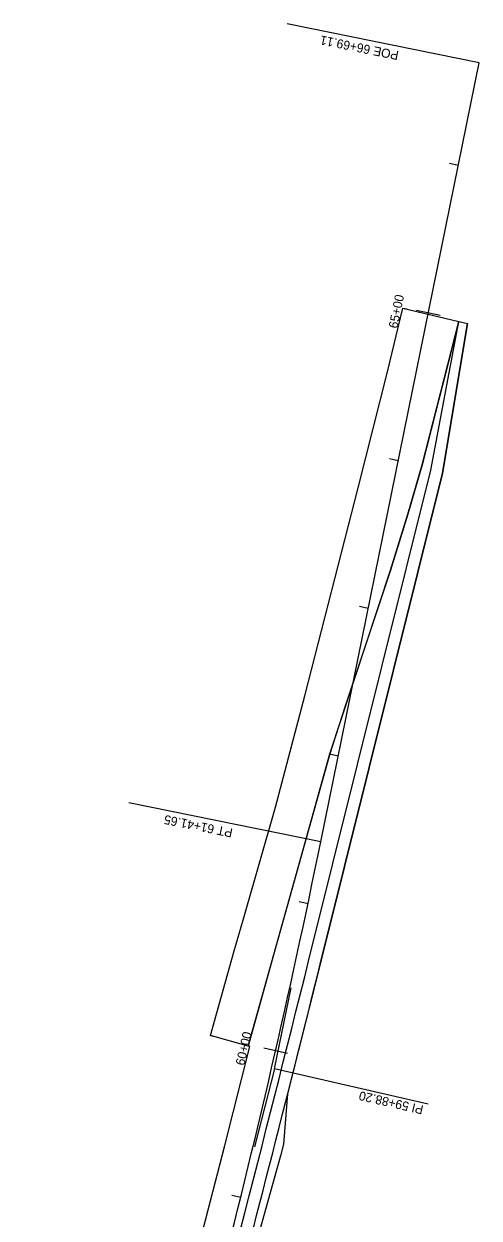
# Model space of a CAD drawing. Extents: x 1445613 to 1446340, y 2042797 to 2056486.
# Drawn here: x 1446038 to 1446340, y 2055693 to 2056486 of the extents above; entities that cross this region are included whole.
import ezdxf

# ---------------------------------------------------------------- set-up
doc = ezdxf.new("R2010")
doc.units = 0
for name, color, linetype in [('20', 7, 'Continuous'), ('Default', 7, 'Continuous'), ('R_Horz Alg', 7, 'Continuous'), ('R_Horz Alg Annot', 7, 'Continuous'), ('R_Horz Alg Annot_Detour', 7, 'Continuous'), ('R_Horz Alg Stationing_Detour', 7, 'Continuous'), ('R_Proposed Road', 7, 'Continuous')]:
    doc.layers.add(name, color=color, linetype=linetype)

msp = doc.modelspace()

# ---------------------------------------------------------------- linework, layer by layer
at = {"layer": '20'}
msp.add_lwpolyline([(1446186.83, 2055807.56), (1446161.85, 2055814.6), (1446177.63, 2055870.73), (1446183.69, 2055891.92), (1446205.01, 2055966.11), (1446224.41, 2056039.93), (1446259.82, 2056178.04), (1446279.28, 2056254.8), (1446289.65, 2056297.22), (1446326.65, 2056288.39), (1446311.26, 2056227.87), (1446302.34, 2056193.19), (1446292.95, 2056160.46), (1446281.38, 2056123.41), (1446261.62, 2056064.35), (1446251, 2056032.33), (1446241.05, 2056001.36), (1446205.13, 2055872.64)], close=True, dxfattribs=at)
msp.add_lwpolyline([(1446133.09, 2055593.77), (1446171.35, 2055741.47), (1446188.04, 2055807.22), (1446186.83, 2055807.56), (1446202.38, 2055862.8), (1446223.09, 2055937), (1446241.05, 2056001.36), (1446281.38, 2056123.41), (1446292.95, 2056160.46), (1446302.34, 2056193.19), (1446326.65, 2056288.39), (1446332.57, 2056286.97), (1446315.99, 2056187.74), (1446234.73, 2055861.84), (1446213.1, 2055775.79), (1446210.29, 2055742.39), (1446208.31, 2055734.63), (1446181.37, 2055638.11)], dxfattribs=at)
at = {"layer": 'Default'}
for p, q in [((1446289.65, 2056297.22), (1446292.2, 2056296.61)), ((1446161.85, 2055814.6), (1446163.78, 2055814.06))]:
    msp.add_line(p, q, dxfattribs=at)
at = {"layer": 'R_Horz Alg'}
msp.add_line((1446235.07, 2055942.97), (1446340.23, 2056459.85), dxfattribs=at)
msp.add_arc((1440620.51, 2057085.26), 5729.58, 345.4304, 348.5, dxfattribs=at)
at = {"layer": 'R_Horz Alg Annot'}
for p, q in [((1446204.46, 2055792.53), (1446215.35, 2055846.09)), ((1446204.46, 2055792.53), (1446190.99, 2055740.71)), ((1446306.45, 2055768.92), (1446204.46, 2055792.53))]:
    msp.add_line(p, q, dxfattribs=at)
at = {"layer": 'R_Horz Alg Annot_Detour'}
for points in [[(1446340.23, 2056459.85), (1446212.84, 2056485.76)], [(1446235.07, 2055942.97), (1446107.67, 2055968.89)]]:
    msp.add_lwpolyline(points, dxfattribs=at)
at = {"layer": 'R_Horz Alg Stationing_Detour'}
for points in [[(1446320.57, 2056393.32), (1446326.45, 2056392.12)], [(1446298.67, 2056295.72), (1446314.35, 2056292.53)], [(1446280.69, 2056197.33), (1446286.57, 2056196.14)], [(1446260.76, 2056099.34), (1446266.64, 2056098.14)], [(1446240.82, 2056001.35), (1446246.7, 2056000.15)], [(1446220.74, 2055903.43), (1446226.61, 2055902.19)], [(1446197.32, 2055806.32), (1446212.91, 2055802.74)], [(1446176.09, 2055708.7), (1446181.91, 2055707.26)]]:
    msp.add_lwpolyline(points, dxfattribs=at)
at = {"layer": 'R_Proposed Road'}
for p, q in [((1446308.23, 2056189.67), (1446326.65, 2056288.39)), ((1446315.99, 2056187.74), (1446332.57, 2056286.97)), ((1446326.65, 2056288.39), (1446332.57, 2056286.97)), ((1446226.97, 2055863.77), (1446308.23, 2056189.67)), ((1446234.73, 2055861.84), (1446315.99, 2056187.74))]:
    msp.add_line(p, q, dxfattribs=at)
for radius, start in [(22947.81, 344.166667), (22955.81, 345.31315)]:
    msp.add_arc((1423960.81, 2061415.35), radius, start, 346, dxfattribs=at)

# ---------------------------------------------------------------- texts
at = {"layer": 'R_Horz Alg Annot_Detour'}
for s, rotation, p in [('POE 66+69.11', 168.5, (1446287.2, 2056467.57)), ('PT 61+41.65', 168.5, (1446177.01, 2055951.72)), ('PI 59+88.20', 167.1077, (1446303.67, 2055767.99))]:
    msp.add_text(s, height=6, rotation=rotation, dxfattribs=at).set_placement(p)
at = {"layer": 'R_Horz Alg Stationing_Detour'}
for s, rotation, p in [('65+00', 78.5, (1446285.95, 2056283.37)), ('60+00', 77.08355, (1446184.29, 2055794.28))]:
    msp.add_text(s, height=6, rotation=rotation, dxfattribs=at).set_placement(p)

doc.saveas('drawing.dxf')
